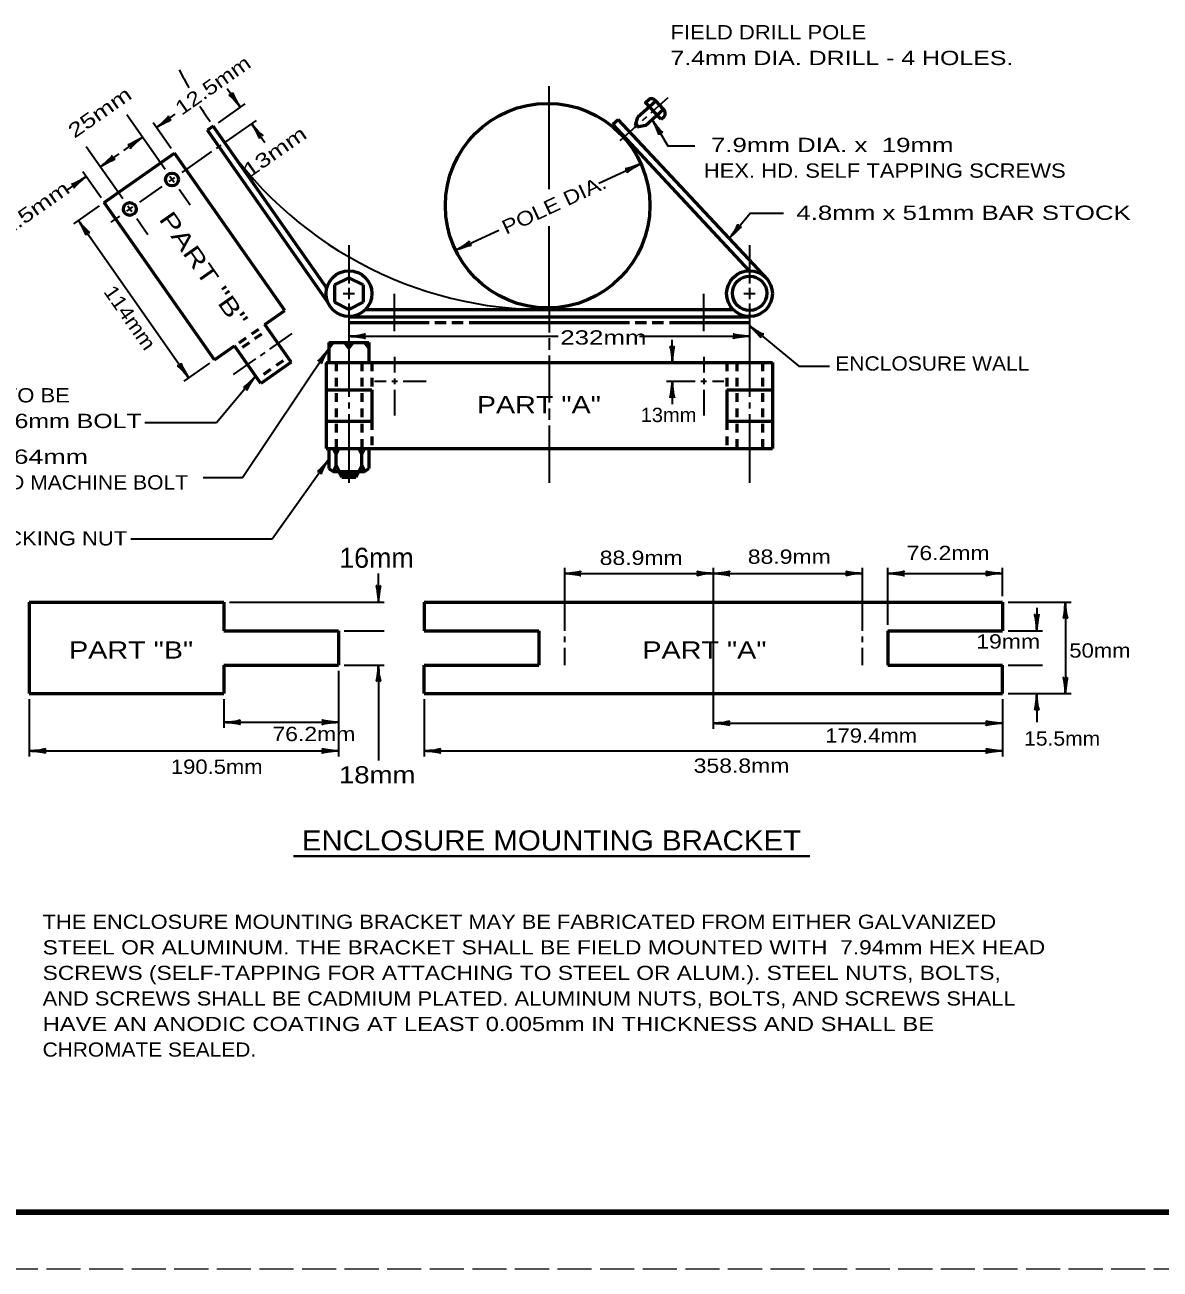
# Model space of a CAD drawing. Extents: x -77 to 603, y -47 to 393.
# Drawn here: x 203.2 to 403.1, y -46.8 to 172.3 of the extents above; entities that cross this region are included whole.
import ezdxf

# ---------------------------------------------------------------- set-up
doc = ezdxf.new("R2010")
doc.units = 0
doc.linetypes.add('LONG_DASHED', pattern=[7.5, 6, -1.5])
doc.linetypes.add('SHORT_DASHED', pattern=[2.7, 1.5, -1.2])
doc.layers.add('1', color=7, linetype='Continuous', lineweight=53)
doc.layers.add('61', color=7, linetype='Continuous', lineweight=35)

msp = doc.modelspace()

# ---------------------------------------------------------------- linework, layer by layer
at = {"layer": '1', "lineweight": 35}
for p, q in [((238.838, 161.114), (241.158, 157.814)), ((295.558, 143.374), (295.558, 161.514)), ((241.978, 158.394), (237.238, 155.054)), ((313.878, 157.174), (316.518, 159.534)), ((227.918, 146.854), (221.18, 156.458)), ((226.418, 154.254), (229.718, 156.574)), ((312.018, 155.494), (312.758, 156.174)), ((313.518, 156.834), (313.878, 157.174)), ((229.018, 150.534), (225.838, 155.074)), ((238.638, 151.734), (243.998, 155.494)), ((243.178, 154.914), (245.498, 151.614)), ((220.638, 150.214), (223.938, 152.514)), ((220.478, 141.654), (214.025, 150.865)), ((216.498, 147.314), (219.818, 149.634)), ((230.898, 146.314), (236.158, 149.994)), ((236.978, 150.574), (237.818, 151.154)), ((304.298, 144.414), (311.718, 147.854)), ((210.718, 143.274), (214.038, 145.574)), ((216.638, 141.874), (213.458, 146.414)), ((228.618, 144.734), (229.658, 145.454)), ((229.498, 144.574), (228.778, 145.614)), ((223.478, 141.114), (227.398, 143.854)), ((232.318, 140.554), (230.378, 143.334)), ((211.838, 137.274), (216.378, 140.454)), ((221.198, 139.534), (222.238, 140.254)), ((222.058, 139.374), (221.338, 140.414)), ((218.398, 137.574), (219.958, 138.654)), ((224.898, 135.334), (222.938, 138.134)), ((212.678, 137.854), (232.078, 110.134)), ((279.078, 132.634), (286.678, 136.194)), ((295.558, 122.174), (295.558, 136.854)), ((260.278, 133.514), (260.278, 126.754)), ((330.838, 133.514), (330.838, 126.754)), ((259.278, 124.994), (261.298, 124.994)), ((260.278, 125.994), (260.278, 123.994)), ((268.338, 118.394), (268.338, 124.934)), ((322.778, 118.394), (322.778, 124.934)), ((329.838, 124.994), (331.858, 124.994)), ((330.838, 125.994), (330.838, 123.994)), ((330.838, 123.234), (330.838, 106.794)), ((295.558, 122.174), (295.558, 118.134)), ((246.358, 115.214), (250.278, 117.974)), ((260.278, 117.494), (297.158, 117.494)), ((260.278, 116.374), (260.278, 106.794)), ((295.558, 117.134), (295.558, 115.114)), ((311.485, 117.494), (330.838, 117.494)), ((317.238, 112.854), (317.238, 116.874)), ((256.758, 115.294), (241.558, 92.534)), ((244.718, 114.054), (245.538, 114.634)), ((295.558, 114.114), (295.558, 105.794)), ((231.258, 109.554), (235.798, 112.734)), ((239.958, 110.734), (243.878, 113.494)), ((268.338, 113.854), (268.338, 111.074)), ((322.778, 113.854), (322.778, 111.074)), ((243.858, 110.434), (236.998, 102.254)), ((264.818, 109.574), (266.838, 109.574)), ((267.838, 109.574), (268.858, 109.574)), ((268.338, 110.074), (268.338, 109.074)), ((269.858, 109.574), (273.898, 109.574)), ((316.218, 109.574), (321.258, 109.574)), ((317.238, 109.574), (317.238, 105.534)), ((322.278, 109.574), (323.278, 109.574)), ((322.778, 110.074), (322.778, 109.074)), ((324.298, 109.574), (326.298, 109.574)), ((268.338, 108.054), (268.338, 103.514)), ((322.778, 108.054), (322.778, 103.514)), ((260.278, 105.794), (260.278, 104.774)), ((330.838, 105.794), (330.838, 104.774)), ((260.278, 103.774), (260.278, 91.674)), ((295.558, 104.774), (295.558, 102.774)), ((330.838, 103.774), (330.838, 91.674)), ((236.998, 102.254), (224.338, 102.254)), ((295.558, 101.754), (295.558, 91.674)), ((256.758, 95.794), (246.788, 81.774)), ((241.558, 92.534), (234.598, 92.534)), ((246.788, 81.774), (221.902, 81.774)), ((298.258, 76.734), (298.258, 65.634)), ((324.458, 76.734), (324.458, 48.334)), ((350.678, 76.734), (350.678, 65.634)), ((355.198, 66.654), (355.198, 76.734)), ((375.358, 71.694), (375.358, 76.734)), ((265.498, 70.674), (265.498, 75.714)), ((355.198, 75.714), (375.358, 75.714)), ((239.278, 70.674), (266.498, 70.674)), ((376.378, 70.674), (387.458, 70.674)), ((386.458, 70.674), (386.458, 54.554)), ((381.418, 69.674), (381.418, 65.634)), ((259.438, 65.634), (266.498, 65.634)), ((298.258, 64.634), (298.258, 63.634)), ((350.678, 64.634), (350.678, 63.634)), ((376.378, 65.634), (382.418, 65.634)), ((298.258, 62.614), (298.258, 59.594)), ((350.678, 62.614), (350.678, 59.594)), ((259.438, 59.594), (266.498, 59.594)), ((265.498, 59.594), (265.498, 42.78)), ((376.378, 59.594), (382.418, 59.594)), ((258.438, 58.594), (258.438, 43.474)), ((203.998, 53.554), (203.998, 43.474)), ((238.278, 53.554), (238.278, 48.514)), ((273.558, 53.554), (273.558, 43.474)), ((375.358, 53.554), (375.358, 43.474)), ((376.378, 54.554), (387.458, 54.554)), ((381.418, 54.554), (381.418, 49.514)), ((238.278, 49.514), (258.438, 49.514)), ((324.458, 49.354), (375.358, 49.354)), ((203.998, 44.474), (258.438, 44.474)), ((273.558, 44.474), (375.358, 44.474))]:
    msp.add_line(p, q, dxfattribs=at)
at = {"layer": '1'}
for p, q in [((311.138, 156.054), (314.318, 158.934)), ((315.698, 157.454), (314.318, 158.934)), ((306.778, 154.814), (307.698, 155.674)), ((334.038, 127.454), (307.698, 155.674)), ((311.138, 156.054), (310.718, 154.674)), ((312.518, 154.594), (315.698, 157.454)), ((315.258, 155.714), (315.778, 156.174)), ((236.398, 154.474), (235.378, 153.754)), ((256.518, 123.554), (235.378, 153.754)), ((256.378, 125.954), (236.398, 154.474)), ((330.838, 129.014), (306.778, 154.814)), ((311.058, 154.294), (310.718, 154.674)), ((312.518, 154.594), (311.058, 154.294)), ((217.218, 141.034), (229.598, 149.714)), ((248.998, 121.994), (229.598, 149.714)), ((236.618, 113.314), (217.218, 141.034)), ((257.758, 126.514), (257.758, 123.474)), ((262.798, 126.514), (262.798, 123.474)), ((260.278, 122.214), (257.758, 123.474)), ((260.278, 122.214), (262.798, 123.474)), ((245.498, 119.534), (248.998, 121.994)), ((260.278, 120.914), (330.838, 120.914)), ((250.118, 112.934), (245.498, 119.534)), ((260.278, 119.894), (274.398, 119.894)), ((275.398, 119.894), (277.418, 119.894)), ((278.418, 119.894), (280.438, 119.894)), ((310.678, 119.894), (312.698, 119.894)), ((313.698, 119.894), (315.718, 119.894)), ((316.738, 119.894), (330.838, 119.894)), ((256.758, 116.374), (256.758, 112.854)), ((256.758, 115.374), (257.518, 116.374)), ((263.058, 116.374), (263.818, 115.374)), ((263.818, 116.374), (263.818, 112.854)), ((236.618, 113.314), (240.138, 115.774)), ((244.758, 109.174), (240.138, 115.774)), ((250.118, 112.934), (244.758, 109.174)), ((256.258, 112.854), (334.878, 112.854)), ((256.258, 112.854), (256.258, 97.734)), ((334.878, 112.854), (334.878, 97.734)), ((256.258, 108.054), (264.318, 108.054)), ((264.318, 108.054), (264.318, 102.514)), ((326.818, 108.054), (334.878, 108.054)), ((326.818, 108.054), (326.818, 102.514)), ((256.258, 102.514), (264.318, 102.514)), ((326.818, 102.514), (334.878, 102.514)), ((256.258, 97.734), (334.878, 97.734)), ((256.758, 97.734), (256.758, 94.194)), ((258.018, 94.694), (258.018, 96.714)), ((262.558, 94.694), (262.558, 96.714)), ((263.818, 97.734), (263.818, 94.194)), ((256.758, 94.194), (257.518, 93.694)), ((257.518, 93.694), (258.518, 93.694)), ((258.518, 93.694), (262.038, 93.694)), ((259.018, 92.694), (258.518, 93.694)), ((258.778, 93.194), (261.798, 93.194)), ((259.018, 92.694), (261.538, 92.694)), ((261.538, 92.694), (262.038, 93.694)), ((262.038, 93.694), (263.058, 93.694)), ((263.058, 93.694), (263.818, 94.194)), ((203.998, 70.674), (238.278, 70.674)), ((203.998, 70.674), (203.998, 54.554)), ((238.278, 70.674), (238.278, 65.634)), ((273.558, 70.674), (273.558, 65.634)), ((273.558, 70.674), (375.358, 70.674)), ((375.358, 70.674), (375.358, 65.634)), ((238.278, 65.634), (258.438, 65.634)), ((258.438, 65.634), (258.438, 59.594)), ((273.558, 65.634), (293.718, 65.634)), ((293.718, 65.634), (293.718, 59.594)), ((355.198, 65.634), (375.358, 65.634)), ((355.198, 65.634), (355.198, 59.594)), ((238.278, 59.594), (258.438, 59.594)), ((238.278, 59.594), (238.278, 54.554)), ((273.558, 59.594), (293.718, 59.594)), ((273.558, 54.554), (273.558, 59.594)), ((355.198, 59.594), (375.358, 59.594)), ((375.358, 54.554), (375.358, 59.594)), ((203.998, 54.554), (238.278, 54.554)), ((273.558, 54.554), (375.358, 54.554))]:
    msp.add_line(p, q, dxfattribs=at)
at = {"layer": '1', "linetype": 'SHORT_DASHED'}
for p, q in [((240.958, 116.354), (244.678, 118.954)), ((241.538, 115.534), (245.258, 118.134)), ((248.718, 113.174), (244.998, 110.574)), ((258.018, 112.854), (258.018, 97.734)), ((262.558, 112.854), (262.558, 97.734)), ((264.318, 112.854), (264.318, 108.054)), ((326.818, 112.854), (326.818, 108.054)), ((328.578, 112.854), (328.578, 97.734)), ((333.118, 112.854), (333.118, 97.734)), ((264.318, 102.514), (264.318, 97.734)), ((326.818, 102.514), (326.818, 97.734))]:
    msp.add_line(p, q, dxfattribs=at)
at = {"layer": '1', "lineweight": 40}
msp.add_line((250.547, 25.925), (341.468, 25.925), dxfattribs=at)
at = {"layer": '1'}
for points in [[(315.258, 155.714), (312.518, 158.654), (313.078, 159.154)], [(257.758, 126.514), (260.278, 127.774), (262.798, 126.514)], [(263.178, 122.174), (295.558, 122.174), (327.958, 122.174)], [(281.458, 119.894), (295.558, 119.894), (309.678, 119.894)], [(256.758, 116.374), (260.278, 116.374), (263.818, 116.374)], [(259.518, 116.374), (260.278, 115.374), (261.038, 116.374)], [(257.518, 97.734), (258.018, 96.714), (258.518, 97.734)], [(262.038, 97.734), (262.558, 96.714), (263.058, 97.734)], [(257.518, 93.694), (258.018, 94.694), (258.518, 93.694)], [(262.038, 93.694), (262.558, 94.694), (263.058, 93.694)]]:
    msp.add_lwpolyline(points, dxfattribs=at)
at = {"layer": '1', "lineweight": 35}
for points in [[(313.698, 155.654), (316.438, 151.014), (321.218, 151.014)], [(308.078, 151.954), (310.898, 154.474), (311.258, 154.814)], [(327.258, 134.714), (330.958, 139.174), (336.838, 139.174)], [(260.278, 123.234), (260.278, 119.894), (260.278, 116.374)], [(330.838, 119.354), (339.518, 112.194), (344.938, 112.194)], [(298.258, 75.714), (324.458, 75.714), (350.678, 75.714)]]:
    msp.add_lwpolyline(points, dxfattribs=at)
at = {"layer": '1'}
for centre, radius in [((295.287, 140.479), 18.012), ((229.141, 145.091), 1.134), ((221.709, 139.892), 1.134), ((260.305, 124.993), 4.032), ((330.838, 124.989), 4.032), ((330.844, 125.048), 3.024)]:
    msp.add_circle(centre, radius, dxfattribs=at)
at = {"layer": '1', "lineweight": 35}
for centre, radius, start, end in [((299.254, 199.233), 77.151, 206.85259, 209.53058), ((299.254, 199.233), 77.151, 212.30043, 214.71143), ((294.817, 190.993), 68.827, 212.77906, 270.62148)]:
    msp.add_arc(centre, radius, start, end, dxfattribs=at)
at = {"layer": '1'}
for centre, start, end in [((313.575, 158.375), 36.55151, 122.47574), ((315.064, 156.768), 320.85592, 48.49762)]:
    msp.add_arc(centre, 0.932, start, end, dxfattribs=at)
at = {"layer": '1', "lineweight": 40}
for centre, major_axis, ratio, start_param, end_param in [((240.296, 158.548), (1.161, -1.384), 0.122415, 0.8963533, 3.1415927), ((240.682, 158.854), (-0.871, 1.552), 0.07063, 6.2823074, 8.5597026), ((227.157, 155.113), (-1.384, -1.161), 0.122415, 0.8963533, 3.1415927), ((227.463, 154.727), (1.552, 0.87), 0.07063, 6.2823074, 8.5597026), ((314.091, 154.574), (-0.75, 1.613), 0.07063, 3.1407148, 5.41811), ((314.499, 154.851), (-1.053, 1.468), 0.122415, 0.8963533, 3.1415927), ((243.652, 153.869), (0.87, -1.552), 0.07063, 6.2823074, 8.5597026), ((244.038, 154.175), (-1.161, 1.384), 0.122415, 0.8963533, 3.1415927), ((222.891, 152.046), (1.552, 0.87), 0.07063, 3.1407148, 5.41811), ((222.891, 152.046), (1.552, 0.87), 0.07063, 3.1407148, 5.41811), ((223.197, 151.66), (1.384, 1.161), 0.122415, 0.8963533, 3.1415927), ((223.197, 151.66), (1.384, 1.161), 0.122415, 0.8963533, 3.1415927), ((217.248, 148.174), (-1.384, -1.161), 0.122415, 0.8963533, 3.1415927), ((217.555, 147.789), (1.552, 0.87), 0.07063, 6.2823074, 8.5597026), ((310.603, 147.577), (-1.679, -0.588), 0.07063, 6.2823074, 8.5597026), ((310.603, 147.577), (-1.679, -0.588), 0.07063, 6.2823074, 8.5597026), ((310.838, 147.144), (1.565, 0.903), 0.122415, 0.8963533, 3.1415927), ((310.838, 147.144), (1.565, 0.903), 0.122415, 0.8963533, 3.1415927), ((212.983, 145.108), (1.552, 0.87), 0.07063, 3.1407148, 5.41811), ((213.289, 144.722), (1.384, 1.161), 0.122415, 0.8963533, 3.1415927), ((213.142, 136.812), (-0.87, 1.552), 0.07063, 3.1407148, 5.41811), ((213.142, 136.812), (-0.87, 1.552), 0.07063, 3.1407148, 5.41811), ((213.528, 137.118), (-1.161, 1.384), 0.122415, 0.8963533, 3.1415927), ((213.528, 137.118), (-1.161, 1.384), 0.122415, 0.8963533, 3.1415927), ((327.742, 135.743), (-1.029, -1.485), 0.122415, 0.8963533, 3.1415927), ((328.139, 135.452), (1.267, 1.249), 0.07063, 6.2823074, 8.5597026), ((279.95, 133.356), (-1.565, -0.903), 0.122415, 0.8963533, 3.1415927), ((280.185, 132.923), (1.679, 0.588), 0.07063, 6.2823074, 8.5597026), ((331.58, 118.462), (-1.253, 1.263), 0.07063, 3.1407148, 5.41811), ((331.87, 118.86), (-1.489, 1.024), 0.122415, 0.8963533, 3.1415927), ((261.413, 117.273), (-1.77, 0.177), 0.07063, 3.1407148, 5.41811), ((261.384, 117.765), (-1.8, -0.157), 0.122415, 0.8963533, 3.1415927), ((329.744, 117.208), (1.8, 0.157), 0.122415, 0.8963533, 3.1415927), ((329.714, 117.7), (1.77, -0.177), 0.07063, 3.1407148, 5.41811), ((255.951, 114.476), (1.13, 1.374), 0.07063, 3.1407148, 5.41811), ((255.951, 114.476), (1.13, 1.374), 0.07063, 3.1407148, 5.41811), ((256.377, 114.228), (0.869, 1.584), 0.122415, 0.8963533, 3.1415927), ((256.377, 114.228), (0.869, 1.584), 0.122415, 0.8963533, 3.1415927), ((316.957, 113.946), (0.157, -1.8), 0.122415, 0.8963533, 3.1415927), ((317.449, 113.976), (-0.177, -1.77), 0.07063, 3.1407148, 5.41811), ((231.22, 110.881), (1.161, -1.384), 0.122415, 0.8963533, 3.1415927), ((231.605, 111.187), (0.87, -1.552), 0.07063, 3.1407148, 5.41811), ((242.979, 109.709), (1.273, 1.244), 0.07063, 3.1407148, 5.41811), ((242.979, 109.709), (1.273, 1.244), 0.07063, 3.1407148, 5.41811), ((243.375, 109.416), (1.035, 1.481), 0.122415, 0.8963533, 3.1415927), ((243.375, 109.416), (1.035, 1.481), 0.122415, 0.8963533, 3.1415927), ((317.023, 108.441), (0.177, 1.77), 0.07063, 3.1407148, 5.41811), ((317.514, 108.47), (-0.157, 1.8), 0.122415, 0.8963533, 3.1415927), ((255.927, 94.994), (-1.171, -1.34), 0.07063, 6.2823074, 8.5597026), ((255.927, 94.994), (-1.171, -1.34), 0.07063, 6.2823074, 8.5597026), ((256.345, 94.733), (0.916, 1.558), 0.122415, 0.8963533, 3.1415927), ((256.345, 94.733), (0.916, 1.558), 0.122415, 0.8963533, 3.1415927), ((299.354, 76.002), (-1.8, -0.157), 0.122415, 0.8963533, 3.1415927), ((299.354, 76.002), (-1.8, -0.157), 0.122415, 0.8963533, 3.1415927), ((299.384, 75.51), (-1.77, 0.177), 0.07063, 3.1407148, 5.41811), ((299.384, 75.51), (-1.77, 0.177), 0.07063, 3.1407148, 5.41811), ((323.362, 75.445), (1.8, 0.157), 0.122415, 0.8963533, 3.1415927), ((323.362, 75.445), (1.8, 0.157), 0.122415, 0.8963533, 3.1415927), ((323.333, 75.937), (1.77, -0.177), 0.07063, 3.1407148, 5.41811), ((323.333, 75.937), (1.77, -0.177), 0.07063, 3.1407148, 5.41811), ((325.562, 76.002), (-1.8, -0.157), 0.122415, 0.8963533, 3.1415927), ((325.562, 76.002), (-1.8, -0.157), 0.122415, 0.8963533, 3.1415927), ((325.592, 75.51), (-1.77, 0.177), 0.07063, 3.1407148, 5.41811), ((325.592, 75.51), (-1.77, 0.177), 0.07063, 3.1407148, 5.41811), ((349.57, 75.445), (1.8, 0.157), 0.122415, 0.8963533, 3.1415927), ((349.57, 75.445), (1.8, 0.157), 0.122415, 0.8963533, 3.1415927), ((349.541, 75.937), (1.77, -0.177), 0.07063, 3.1407148, 5.41811), ((349.541, 75.937), (1.77, -0.177), 0.07063, 3.1407148, 5.41811), ((356.306, 76.002), (-1.8, -0.157), 0.122415, 0.8963533, 3.1415927), ((356.336, 75.51), (-1.77, 0.177), 0.07063, 3.1407148, 5.41811), ((374.266, 75.445), (1.8, 0.157), 0.122415, 0.8963533, 3.1415927), ((374.237, 75.937), (1.77, -0.177), 0.07063, 3.1407148, 5.41811), ((265.216, 71.783), (0.157, -1.8), 0.122415, 0.8963533, 3.1415927), ((265.707, 71.813), (-0.177, -1.77), 0.07063, 3.1407148, 5.41811), ((386.241, 69.554), (0.177, 1.77), 0.07063, 3.1407148, 5.41811), ((386.733, 69.583), (-0.157, 1.8), 0.122415, 0.8963533, 3.1415927), ((381.136, 66.743), (0.157, -1.8), 0.122415, 0.8963533, 3.1415927), ((381.627, 66.773), (-0.177, -1.77), 0.07063, 3.1407148, 5.41811), ((265.281, 58.466), (0.177, 1.77), 0.07063, 3.1407148, 5.41811), ((265.773, 58.495), (-0.157, 1.8), 0.122415, 0.8963533, 3.1415927), ((386.176, 55.655), (0.157, -1.8), 0.122415, 0.8963533, 3.1415927), ((386.667, 55.685), (-0.177, -1.77), 0.07063, 3.1407148, 5.41811), ((381.201, 53.426), (0.177, 1.77), 0.07063, 3.1407148, 5.41811), ((381.693, 53.455), (-0.157, 1.8), 0.122415, 0.8963533, 3.1415927), ((239.378, 49.794), (-1.8, -0.157), 0.122415, 0.8963533, 3.1415927), ((239.378, 49.794), (-1.8, -0.157), 0.122415, 0.8963533, 3.1415927), ((239.408, 49.302), (-1.77, 0.177), 0.07063, 3.1407148, 5.41811), ((239.408, 49.302), (-1.77, 0.177), 0.07063, 3.1407148, 5.41811), ((257.338, 49.237), (1.8, 0.157), 0.122415, 0.8963533, 3.1415927), ((257.338, 49.237), (1.8, 0.157), 0.122415, 0.8963533, 3.1415927), ((257.309, 49.729), (1.77, -0.177), 0.07063, 3.1407148, 5.41811), ((257.309, 49.729), (1.77, -0.177), 0.07063, 3.1407148, 5.41811), ((325.562, 49.626), (-1.8, -0.157), 0.122415, 0.8963533, 3.1415927), ((325.562, 49.626), (-1.8, -0.157), 0.122415, 0.8963533, 3.1415927), ((325.592, 49.134), (-1.77, 0.177), 0.07063, 3.1407148, 5.41811), ((325.592, 49.134), (-1.77, 0.177), 0.07063, 3.1407148, 5.41811), ((374.266, 49.069), (1.8, 0.157), 0.122415, 0.8963533, 3.1415927), ((374.266, 49.069), (1.8, 0.157), 0.122415, 0.8963533, 3.1415927), ((374.237, 49.561), (1.77, -0.177), 0.07063, 3.1407148, 5.41811), ((374.237, 49.561), (1.77, -0.177), 0.07063, 3.1407148, 5.41811), ((205.106, 44.754), (-1.8, -0.157), 0.122415, 0.8963533, 3.1415927), ((205.136, 44.262), (-1.77, 0.177), 0.07063, 3.1407148, 5.41811), ((257.338, 44.197), (1.8, 0.157), 0.122415, 0.8963533, 3.1415927), ((257.338, 44.197), (1.8, 0.157), 0.122415, 0.8963533, 3.1415927), ((257.309, 44.689), (1.77, -0.177), 0.07063, 3.1407148, 5.41811), ((257.309, 44.689), (1.77, -0.177), 0.07063, 3.1407148, 5.41811), ((274.658, 44.754), (-1.8, -0.157), 0.122415, 0.8963533, 3.1415927), ((274.688, 44.262), (-1.77, 0.177), 0.07063, 3.1407148, 5.41811), ((374.266, 44.197), (1.8, 0.157), 0.122415, 0.8963533, 3.1415927), ((374.266, 44.197), (1.8, 0.157), 0.122415, 0.8963533, 3.1415927), ((374.237, 44.689), (1.77, -0.177), 0.07063, 3.1407148, 5.41811), ((374.237, 44.689), (1.77, -0.177), 0.07063, 3.1407148, 5.41811)]:
    msp.add_ellipse(centre, major_axis=major_axis, ratio=ratio, start_param=start_param, end_param=end_param, dxfattribs=at)
at = {"layer": '61', "lineweight": 158}
msp.add_line((592.095, -36.776), (-46.965, -36.756), dxfattribs=at)
at = {"layer": '61', "linetype": 'LONG_DASHED', "lineweight": 13}
msp.add_line((603.035, -46.756), (-77.025, -46.776), dxfattribs=at)

# ---------------------------------------------------------------- texts
at = {"layer": '1'}
for s, height, width, p in [('FIELD DRILL POLE', 2.52, 1.15, (316.918, 169.754)), ('7.4mm DIA. DRILL - 4 HOLES.', 2.52, 1.3, (316.918, 165.234)), (' 7.9mm DIA. x  19mm', 2.52, 1.35, (322.778, 149.914)), ('HEX. HD. SELF TAPPING SCREWS', 2.52, 1.15, (322.778, 145.394)), (' 4.8mm x 51mm BAR STOCK', 2.52, 1.35, (337.818, 137.974)), ('232mm ', 2.52, 1.35, (297.518, 116.014)), ('ENCLOSURE WALL', 2.52, 1.1, (345.938, 111.434)), ('FORMED HINGE TO BE', 2.52, 1.15, (168.304, 105.833)), ('PART "A"', 3.024, 1.25, (282.818, 103.914)), ('SNUG FIT ON  16mm BOLT', 2.52, 1.3, (168.304, 101.313)), ('13mm', 2.52, 1.05, (311.664, 102.378)), ('16mm x 64mm ', 2.52, 1.4, (183.147, 95.02)), ('HEX. HEAD MACHINE BOLT', 2.52, 1.1, (183.147, 90.5)), ('HEX. SELF LOCKING NUT', 2.52, 1.15, (173.88, 80.643)), ('88.9mm', 2.52, 1.2, (304.452, 77.215)), ('88.9mm', 2.52, 1.2, (330.533, 77.414)), ('76.2mm', 2.52, 1.2, (358.504, 78.069)), ('PART "B"', 3.024, 1.25, (211.018, 60.734)), ('PART "A"', 3.024, 1.25, (311.978, 60.734)), (' 19mm', 2.52, 1.2, (369.641, 62.489)), ('50mm', 2.52, 1.15, (387.159, 60.898)), ('76.2mm', 2.52, 1.2, (246.818, 46.194)), ('179.4mm', 2.52, 1.15, (344.178, 45.914)), ('15.5mm', 2.52, 1.1, (379.198, 45.394)), ('190.5mm', 2.52, 1.15, (228.938, 40.434)), (' 18mm', 3.024, 1.2, (257.177, 38.757)), ('358.8mm', 2.52, 1.2, (320.998, 40.614)), ('ENCLOSURE MOUNTING BRACKET', 3.528, 1.1, (251.987, 26.945)), ('THE ENCLOSURE MOUNTING BRACKET MAY BE FABRICATED FROM EITHER GALVANIZED', 2.5, 1.15, (206.358, 13.135)), ('STEEL OR ALUMINUM. THE BRACKET SHALL BE FIELD MOUNTED WITH  7.94mm HEX HEAD', 2.5, 1.2, (206.358, 8.635)), ('SCREWS (SELF-TAPPING FOR ATTACHING TO STEEL OR ALUM.). STEEL NUTS, BOLTS,', 2.5, 1.2, (206.358, 4.135)), ('AND SCREWS SHALL BE CADMIUM PLATED. ALUMINUM NUTS, BOLTS, AND SCREWS SHALL', 2.5, 1.15, (206.358, -0.365)), ('HAVE AN ANODIC COATING AT LEAST 0.005mm IN THICKNESS AND SHALL BE', 2.5, 1.25, (206.358, -4.865)), ('CHROMATE SEALED.', 2.5, 1.1, (206.358, -9.365))]:
    msp.add_text(s, height=height, dxfattribs=dict(at, width=width)).set_placement(p)
for s, height, rotation, width, p in [('12.5mm', 2.52, 35.001, 1.25, (230.825, 156.285)), ('25mm', 2.52, 35.001, 1.35, (211.956, 152.25)), (' 13mm', 2.52, 35.001, 1.35, (241.736, 144.582)), ('POLE DIA.', 2.52, 25, 1.2, (287.978, 135.334)), (' 12.5mm', 2.52, 35.001, 1.35, (196.881, 132.755)), ('PART "B"', 3.024, 305, 1.35, (226.718, 138.094)), ('114mm', 2.52, 305, 1.15, (216.978, 125.334))]:
    msp.add_text(s, height=height, rotation=rotation, dxfattribs=dict(at, width=width)).set_placement(p)
msp.add_text('16mm', height=3.528, dxfattribs=at).set_placement((258.591, 76.715))

doc.saveas('drawing.dxf')
